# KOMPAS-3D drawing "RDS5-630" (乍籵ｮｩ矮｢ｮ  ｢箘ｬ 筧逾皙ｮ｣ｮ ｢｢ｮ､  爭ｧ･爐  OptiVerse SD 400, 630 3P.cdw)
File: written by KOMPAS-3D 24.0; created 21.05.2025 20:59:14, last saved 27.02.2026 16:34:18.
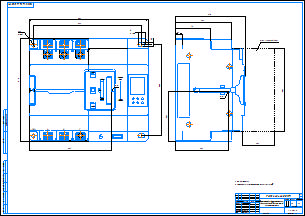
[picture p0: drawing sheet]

Document properties: Утвердил: Строгонов; Автор: keaz-admin; Проверил: Дорошев; Форматы листов документа: A1; Полное имя файла: D:\Проекты\OptiVerse SD\OptiVerse SD\OptiVerse SD 400 3P\КД\ГЖИК.648466.001ГЧ Устройство автоматического ввода резерва OptiVerse SD 400 3P (без рамки).cdw; Масса: 6.7; Т. контр.: Пашков А.Е.; Наименование: Устройство автоматического ввода резерва OptiVerse SD 400 3P / Габаритный чертеж; Н. контр.: Гаврикова; Количество листов документа: 1; Разработал: Сулейманова

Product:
- Body: Тело 1
    Масса: 0.000011
- Component [assembly]: RDS5-630.STEP  | qty 1  | Масса: 72.576943; source file: ..\..\OptiVerse SD 630 3P\3D\Сборка OptiVerse SD 630 3P.a3d
- Part/product: RDS5-630
    Масса: 72.576955
    Форматы листов документа: A1

Views: Проекционный вид 2, Вид 1
Referenced files in C:\Users\user\Desktop\шаблоны Компас\: чертеж с версией.LYT
Referenced files in D:\Проекты\OptiVerse SD\OptiVerse SD\OptiVerse SD 630 3P\КД\: ГЖИК.648476.001СБ Устройство автоматического ввода резерва OptiVerse SD 630 3P.cdw
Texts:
  Зона обслуживания
  Verdana
  LOAD
  Устройство автоматического
  ввода резерва OptiVerse SD 400 3P
  Габаритный чертеж
  ГЖИК.648466.001ГЧ
  Сулейманова
  Дорошев
  ГЖИК.648466.001
  АО "КЭАЗ"
  Гаврикова
  Строгонов
  Пашков А.Е.
  Рамка с версией
Dimensions and other numbers on the sheet: 194; 156; 20; 98; 130; 230; 147; 140; 1:1; 0; 1; 2; 6,7

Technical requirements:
  Ц.М. - центр масс.
  Отклонение координат от центра масс не более 10 %.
